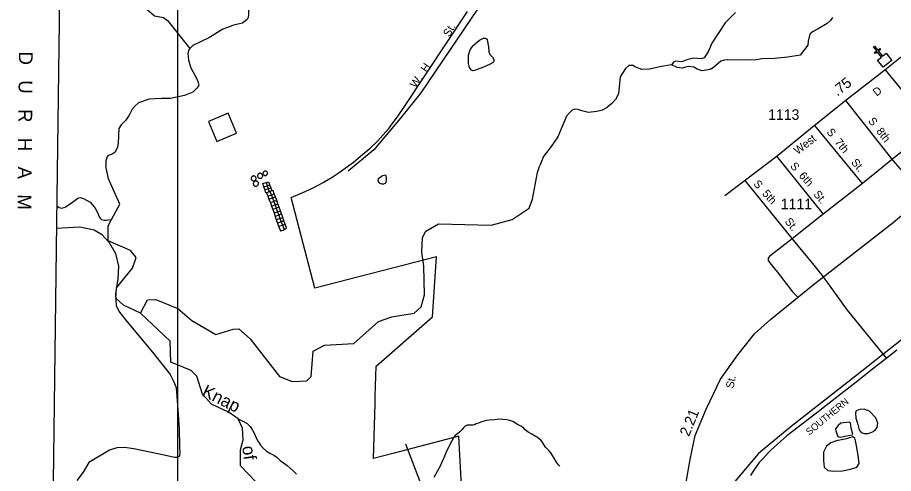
# Model space of a CAD drawing. Extents: x 2056842 to 2160602, y 826753 to 1016856.
# Drawn here: x 2057378 to 2067778, y 860868 to 866278 of the extents above; entities that cross this region are included whole.
import ezdxf

# ---------------------------------------------------------------- set-up
doc = ezdxf.new("R2010")
doc.units = 0
for name, color, linetype in [('Exist Boundary Land Use Reservation Military US Department of Defense', 7, 'Continuous'), ('Exist Boundary Political City Limit New', 7, 'Continuous'), ('Exist Boundary Political CountyLine', 7, 'Continuous'), ('Exist Boundary Political CountyLine Label', 7, 'Continuous'), ('Exist Cultural Church CELL', 7, 'Continuous'), ('Exist Hydrographic Creek Single Shore', 7, 'Continuous'), ('Exist Hydrographic Creek Single Shore Label', 7, 'Continuous'), ('Exist Hydrographic Misc Water Feature', 7, 'Continuous'), ('Exist Railroad Mainline', 7, 'Continuous'), ('Exist Railroad Mainline Label', 7, 'Continuous'), ('Exist Road Non-System Type 51', 7, 'Continuous'), ('Exist Road Non-System Type 51 Label', 7, 'Continuous'), ('Exist Road Secondary Mileage Hundredths English Label', 7, 'Continuous'), ('Exist Road Secondary Type 51 Attributed', 7, 'Continuous'), ('Exist Road Secondary Type 51 Label', 7, 'Continuous'), ('Exist Road Secondary Type 51 Number Label', 7, 'Continuous'), ('Map Preparation Boundary City Limit Buffer Line', 7, 'Continuous'), ('Map Preparation Inset Cut Line', 7, 'Continuous')]:
    doc.layers.add(name, color=color, linetype=linetype)

msp = doc.modelspace()

# ---------------------------------------------------------------- linework, layer by layer
at = {"layer": 'Exist Boundary Land Use Reservation Military US Department of Defense'}
msp.add_lwpolyline([(2068119, 862646), (2067327, 862022), (2066562, 861424), (2066175, 861104), (2065853, 860720)], dxfattribs=at)
at = {"layer": 'Exist Boundary Political City Limit New'}
for points in [[(2061626, 861786), (2061636, 862140), (2062304, 862726), (2062353, 863437), (2060909, 863065), (2060628, 864143), (2060756, 864197), (2060887, 864258), (2061006, 864321), (2061116, 864385), (2061208, 864447), (2061239, 864469), (2061367, 864563), (2061475, 864651), (2061566, 864729), (2061653, 864812), (2061717, 864881), (2061791, 864966), (2061815, 865000), (2061888, 865101), (2061972, 865223), (2062721, 866349)], [(2062676, 860203), (2062618, 861310), (2061851, 861109), (2061604, 861044), (2061623, 861697), (2061626, 861786)]]:
    msp.add_lwpolyline(points, dxfattribs=at)
at = {"layer": 'Exist Boundary Political CountyLine'}
msp.add_lwpolyline([(2058297, 904796), (2058304, 899211), (2058216, 894228), (2058154, 887047), (2058114, 884097), (2057934, 870695), (2057845, 864146), (2057782, 859231), (2057748, 856800), (2057704, 853375), (2057690, 853331), (2057682, 853305), (2057672, 853284), (2057665, 853266), (2057651, 853246), (2057635, 853225), (2057616, 853207), (2057583, 853188)], dxfattribs=at)
at = {"layer": 'Exist Cultural Church CELL'}
msp.add_lwpolyline([(2067590, 865774), (2067635, 865809), (2067588, 865869), (2067563, 865850), (2067553, 865862), (2067579, 865882), (2067542, 865930), (2067554, 865939), (2067591, 865892), (2067617, 865911), (2067626, 865899), (2067601, 865879), (2067648, 865819), (2067693, 865854), (2067759, 865770), (2067655, 865690)], close=True, dxfattribs=at)
at = {"layer": 'Exist Hydrographic Creek Single Shore'}
for points in [[(2060205, 867203), (2060148, 866697), (2060125, 866448), (2060120, 866318), (2060116, 866278)], [(2065904, 866337), (2065782, 866215), (2065622, 865972), (2065578, 865871), (2065531, 865798), (2065496, 865786), (2065407, 865794), (2065324, 865777), (2065264, 865753), (2065192, 865761), (2065169, 865753), (2065144, 865717)], [(2060116, 866278), (2060104, 866254), (2060048, 866213), (2059944, 866189), (2059913, 866177), (2059815, 866140), (2059656, 866041), (2059458, 865945), (2059423, 865910)], [(2067056, 866279), (2067032, 866243), (2066992, 866207), (2066886, 866144), (2066816, 866108), (2066784, 866080), (2066764, 865996), (2066760, 865952), (2066669, 865832), (2066523, 865806), (2066365, 865791), (2066221, 865787), (2066147, 865775), (2066051, 865771), (2065811, 865778), (2065767, 865774), (2065727, 865762), (2065643, 865686), (2065603, 865662), (2065507, 865646), (2065447, 865664), (2065407, 865690), (2065347, 865696), (2065311, 865688), (2065275, 865679), (2065212, 865685), (2065144, 865717)], [(2059423, 865910), (2059411, 865896), (2059401, 865850), (2059409, 865772), (2059437, 865682), (2059509, 865549), (2059524, 865509), (2059532, 865476), (2059509, 865438), (2059461, 865392), (2059362, 865354), (2059195, 865318), (2059083, 865317), (2058942, 865310), (2058816, 865264), (2058773, 865227), (2058740, 865190), (2058702, 865120), (2058665, 865061), (2058608, 865004), (2058583, 864961), (2058573, 864793), (2058567, 864741), (2058539, 864679), (2058501, 864655), (2058454, 864642), (2058443, 864627), (2058428, 864577), (2058426, 864547), (2058427, 864519)], [(2065144, 865717), (2065003, 865695), (2064883, 865667), (2064791, 865663), (2064707, 865694), (2064687, 865710), (2064635, 865710), (2064595, 865674), (2064535, 865574), (2064512, 865374), (2064478, 865304), (2064438, 865260), (2064378, 865210), (2064318, 865178), (2064258, 865162), (2064158, 865153), (2064078, 865169), (2064036, 865185), (2063992, 865189), (2063962, 865177), (2063926, 865145), (2063896, 865109), (2063792, 864861), (2063715, 864749), (2063625, 864630), (2063581, 864522)], [(2058839, 862771), (2058638, 862864), (2058547, 862948), (2058555, 863072), (2058745, 863305), (2058788, 863432), (2058720, 863515), (2058454, 863629), (2058454, 863806), (2058493, 863881), (2058595, 864063), (2058460, 864364), (2058427, 864519)], [(2058839, 862771), (2058922, 862930), (2059021, 862931), (2059280, 862824), (2059447, 862683), (2059731, 862517), (2059938, 862581), (2060006, 862583), (2060139, 862465), (2060489, 862019), (2060640, 861960), (2060814, 861969), (2060864, 862017), (2060890, 862319), (2061023, 862391), (2061373, 862411), (2061664, 862670), (2061821, 862726), (2062088, 862770), (2062171, 862844), (2062212, 862987), (2062203, 863329), (2062178, 863496), (2062186, 863670), (2062227, 863745), (2062378, 863830), (2063003, 863814), (2063253, 863881), (2063452, 864015), (2063493, 864122), (2063551, 864439), (2063581, 864522)], [(2060209, 860768), (2060025, 860958), (2060025, 861149), (2060058, 861266), (2060050, 861407), (2059999, 861517), (2059890, 861591), (2059683, 861691), (2059573, 861808), (2059507, 862022), (2059440, 862089), (2059198, 862190), (2059190, 862439), (2058839, 862771)], [(2059999, 861517), (2060062, 861486), (2060106, 861460), (2060141, 861426), (2060168, 861381), (2060191, 861337), (2060213, 861292), (2060235, 861247), (2060263, 861206), (2060296, 861168), (2060333, 861134), (2060376, 861109), (2060421, 861086), (2060460, 861056), (2060498, 861023), (2060538, 860993), (2060578, 860963), (2060617, 860931), (2060654, 860897), (2060690, 860862)], [(2063818, 860953), (2063801, 860969), (2063777, 861001), (2063749, 861051), (2063709, 861113), (2063689, 861137), (2063671, 861157), (2063647, 861181), (2063635, 861199), (2063607, 861243), (2063591, 861263), (2063576, 861277), (2063547, 861299), (2063525, 861312), (2063485, 861336), (2063443, 861360), (2063405, 861388), (2063384, 861408), (2063354, 861428), (2063321, 861446), (2063289, 861466), (2063260, 861484), (2063225, 861498), (2063188, 861504), (2063138, 861510), (2063092, 861512), (2063040, 861506), (2062978, 861501), (2062946, 861496), (2062887, 861479), (2062850, 861467), (2062823, 861457), (2062804, 861447), (2062785, 861443), (2062765, 861441), (2062752, 861441), (2062732, 861443), (2062715, 861441), (2062695, 861429), (2062673, 861409), (2062655, 861387), (2062643, 861375), (2062626, 861359), (2062605, 861343), (2062576, 861319), (2062559, 861301), (2062529, 861246), (2062495, 861181), (2062465, 861114), (2062441, 861052), (2062417, 861003), (2062395, 860954), (2062361, 860893), (2062320, 860821)]]:
    msp.add_lwpolyline(points, dxfattribs=at)
at = {"layer": 'Exist Hydrographic Misc Water Feature'}
for p, q in [((2059743, 864808), (2059979, 864906)), ((2060304, 864270), (2060342, 864282)), ((2060316, 864236), (2060304, 864270)), ((2060330, 864319), (2060342, 864282)), ((2060342, 864282), (2060372, 864292)), ((2060342, 864282), (2060354, 864246)), ((2060354, 864246), (2060384, 864256)), ((2060372, 864292), (2060384, 864256)), ((2060384, 864256), (2060398, 864221)), ((2060316, 864236), (2060354, 864246)), ((2060366, 864210), (2060334, 864200)), ((2060334, 864200), (2060350, 864161)), ((2060350, 864161), (2060392, 864172)), ((2060350, 864161), (2060364, 864122)), ((2060354, 864246), (2060366, 864210)), ((2060398, 864221), (2060376, 864215)), ((2060376, 864215), (2060392, 864172)), ((2060392, 864172), (2060425, 864187)), ((2060392, 864172), (2060406, 864137)), ((2060406, 864137), (2060442, 864149)), ((2060456, 864109), (2060442, 864149)), ((2060364, 864122), (2060406, 864137)), ((2060364, 864122), (2060380, 864080)), ((2060420, 864097), (2060380, 864080)), ((2060394, 864041), (2060436, 864055)), ((2060406, 864137), (2060420, 864097)), ((2060456, 864109), (2060420, 864097)), ((2060420, 864097), (2060436, 864055)), ((2060436, 864055), (2060470, 864067)), ((2060436, 864055), (2060450, 864015)), ((2060484, 864027), (2060470, 864067)), ((2060394, 864041), (2060408, 864001)), ((2060450, 864015), (2060408, 864001)), ((2060408, 864001), (2060424, 863961)), ((2060424, 863961), (2060466, 863972)), ((2060424, 863961), (2060436, 863919)), ((2060484, 864027), (2060450, 864015)), ((2060450, 864015), (2060466, 863972)), ((2060466, 863972), (2060500, 863985)), ((2060466, 863972), (2060480, 863935)), ((2060514, 863947), (2060480, 863935)), ((2060500, 863985), (2060484, 864027)), ((2060514, 863947), (2060500, 863985)), ((2060480, 863935), (2060436, 863919)), ((2060436, 863919), (2060450, 863881)), ((2060450, 863881), (2060494, 863895)), ((2060510, 863855), (2060464, 863839)), ((2060464, 863839), (2060478, 863801)), ((2060480, 863935), (2060494, 863895)), ((2060494, 863895), (2060528, 863905)), ((2060494, 863895), (2060510, 863855)), ((2060542, 863867), (2060510, 863855)), ((2060510, 863855), (2060525, 863815)), ((2060542, 863867), (2060528, 863905)), ((2060556, 863827), (2060542, 863867)), ((2060478, 863801), (2060525, 863815)), ((2060525, 863815), (2060556, 863827)), ((2060525, 863815), (2060543, 863763))]:
    msp.add_line(p, q, dxfattribs=at)
for points in [[(2057891, 867490), (2058055, 867172), (2058231, 866826), (2058332, 866695), (2058362, 866643), (2058378, 866599), (2058410, 866563), (2058498, 866495), (2058634, 866405), (2058674, 866422), (2058718, 866473), (2058768, 866482), (2058814, 866472), (2058850, 866452), (2058890, 866396), (2058972, 866326), (2059006, 866300), (2059112, 866279), (2059160, 866242), (2059423, 865911)], [(2062912, 865691), (2062804, 865648), (2062784, 865646), (2062767, 865653), (2062743, 865687), (2062732, 865734), (2062733, 865831), (2062751, 865894), (2062787, 865945), (2062865, 866009), (2062912, 866035), (2062929, 866033), (2062946, 866027), (2062953, 866013), (2062971, 865929), (2062974, 865870), (2062986, 865839), (2063019, 865807), (2063032, 865779), (2063033, 865760), (2063027, 865743), (2062991, 865724), (2062912, 865691)], [(2059769, 865096), (2059646, 865043), (2059743, 864808)], [(2059979, 864906), (2059878, 865142), (2059769, 865096)], [(2060186, 864398), (2060182, 864398), (2060176, 864396), (2060170, 864396), (2060164, 864392), (2060160, 864388), (2060158, 864384), (2060156, 864378), (2060154, 864374), (2060154, 864368), (2060154, 864362), (2060158, 864356), (2060160, 864350), (2060164, 864348), (2060168, 864344), (2060172, 864342), (2060178, 864340), (2060184, 864340), (2060188, 864342), (2060194, 864344), (2060200, 864346), (2060204, 864350), (2060206, 864354), (2060208, 864360), (2060210, 864364), (2060210, 864370), (2060210, 864376), (2060208, 864382), (2060204, 864388), (2060198, 864392), (2060194, 864396), (2060190, 864396), (2060186, 864398)], [(2060263, 864431), (2060257, 864431), (2060253, 864429), (2060246, 864427), (2060240, 864425), (2060236, 864421), (2060234, 864417), (2060230, 864411), (2060229, 864405), (2060228, 864399), (2060229, 864395), (2060231, 864389), (2060233, 864383), (2060237, 864379), (2060240, 864377), (2060242, 864373), (2060248, 864371), (2060253, 864371), (2060259, 864369), (2060264, 864371), (2060269, 864371), (2060275, 864373), (2060279, 864377), (2060283, 864383), (2060287, 864387), (2060289, 864391), (2060288, 864395), (2060289, 864401), (2060288, 864405), (2060287, 864409), (2060286, 864413), (2060285, 864417), (2060280, 864421), (2060274, 864425), (2060268, 864429), (2060263, 864431)], [(2060327, 864455), (2060320, 864457), (2060317, 864457), (2060310, 864455), (2060305, 864453), (2060301, 864449), (2060296, 864443), (2060293, 864437), (2060292, 864431), (2060293, 864427), (2060292, 864421), (2060296, 864415), (2060301, 864411), (2060302, 864407), (2060309, 864405), (2060315, 864403), (2060320, 864403), (2060325, 864403), (2060331, 864405), (2060336, 864407), (2060338, 864411), (2060342, 864415), (2060344, 864419), (2060347, 864425), (2060346, 864431), (2060344, 864437), (2060345, 864441), (2060341, 864445), (2060338, 864449), (2060334, 864453), (2060331, 864455), (2060327, 864455)], [(2061693, 864385), (2061662, 864364), (2061658, 864343), (2061672, 864316), (2061698, 864303), (2061727, 864304), (2061748, 864314), (2061759, 864335), (2061758, 864377), (2061750, 864405), (2061738, 864409), (2061713, 864400), (2061693, 864385)], [(2060201, 864278), (2060207, 864276), (2060211, 864276), (2060217, 864276), (2060223, 864280), (2060228, 864284), (2060233, 864288), (2060237, 864292), (2060236, 864296), (2060239, 864300), (2060239, 864307), (2060239, 864310), (2060239, 864316), (2060237, 864322), (2060233, 864328), (2060226, 864332), (2060223, 864334), (2060219, 864336), (2060212, 864338), (2060209, 864338), (2060202, 864338), (2060199, 864338), (2060193, 864334), (2060189, 864330), (2060185, 864326), (2060183, 864322), (2060179, 864316), (2060177, 864310), (2060177, 864304), (2060179, 864300), (2060180, 864294), (2060183, 864288), (2060186, 864284), (2060191, 864282), (2060196, 864278), (2060201, 864278)], [(2060304, 864270), (2060292, 864307), (2060330, 864319)], [(2060330, 864319), (2060359, 864329), (2060372, 864296), (2060372, 864292)], [(2060334, 864200), (2060328, 864198), (2060316, 864236)], [(2060376, 864215), (2060370, 864212), (2060366, 864210)], [(2060425, 864187), (2060412, 864227), (2060398, 864221)], [(2060442, 864149), (2060433, 864169), (2060425, 864187)], [(2057844, 864045), (2057873, 864023), (2057905, 864017), (2057943, 864029), (2058030, 864088), (2058093, 864136), (2058119, 864142), (2058163, 864132), (2058240, 864087), (2058288, 864031), (2058310, 864001), (2058330, 863955), (2058344, 863923), (2058361, 863897), (2058377, 863883), (2058407, 863873), (2058434, 863875), (2058456, 863879), (2058493, 863881)], [(2060380, 864080), (2060384, 864066), (2060394, 864041)], [(2060470, 864067), (2060460, 864095), (2060456, 864109)], [(2060528, 863905), (2060520, 863929), (2060514, 863947)], [(2060450, 863881), (2060462, 863845), (2060464, 863839)], [(2060478, 863801), (2060499, 863749), (2060505, 863749), (2060517, 863751), (2060532, 863757), (2060543, 863763)], [(2060543, 863763), (2060552, 863767), (2060572, 863781), (2060556, 863827)], [(2067352, 861466), (2067371, 861388), (2067394, 861354), (2067432, 861344), (2067478, 861344), (2067520, 861357), (2067556, 861380), (2067586, 861414), (2067592, 861464), (2067569, 861530), (2067493, 861606), (2067430, 861631), (2067379, 861627), (2067337, 861612), (2067326, 861589), (2067333, 861525), (2067352, 861466)], [(2067278, 861407), (2067269, 861471), (2067252, 861477), (2067155, 861466), (2067120, 861439), (2067090, 861397), (2067096, 861376), (2067113, 861314), (2067128, 861302), (2067155, 861298), (2067202, 861312), (2067290, 861325), (2067295, 861335), (2067278, 861407)], [(2067219, 861281), (2067103, 861255), (2067035, 861232), (2066985, 861194), (2066949, 861120), (2066947, 861021), (2066955, 860945), (2066999, 860903), (2067071, 860897), (2067174, 860901), (2067267, 860918), (2067345, 860943), (2067371, 860985), (2067360, 861084), (2067330, 861241), (2067318, 861289), (2067295, 861302), (2067244, 861289), (2067219, 861281)]]:
    msp.add_lwpolyline(points, dxfattribs=at)
at = {"layer": 'Exist Railroad Mainline'}
msp.add_lwpolyline([(2067817, 862332), (2067722, 862256), (2067494, 862077), (2067392, 861995), (2067315, 861935), (2067230, 861870), (2067156, 861814), (2066980, 861675), (2066884, 861599), (2066786, 861523), (2066648, 861416), (2066514, 861313), (2066363, 861182), (2066323, 861145), (2066290, 861112), (2066227, 861043), (2066184, 860998), (2066149, 860948), (2066111, 860895), (2066082, 860846)], dxfattribs=at)
at = {"layer": 'Exist Road Non-System Type 51'}
for p, q in [((2067679, 865659), (2068254, 864952)), ((2067210, 865293), (2067771, 864581)), ((2067410, 864309), (2066843, 864998)), ((2066391, 864635), (2066944, 863943))]:
    msp.add_line(p, q, dxfattribs=at)
for points in [[(2063128, 866745), (2063066, 866682), (2062940, 866527), (2062165, 865385), (2061925, 865082), (2061608, 864708), (2061305, 864455)], [(2067771, 864581), (2067909, 864423), (2068132, 864148)], [(2066013, 864345), (2066572, 863658)], [(2057840, 863778), (2058120, 863795), (2058289, 863760), (2058376, 863708), (2058467, 863608), (2058541, 863478), (2058576, 863326), (2058571, 863178), (2058541, 863000), (2058549, 862857), (2058589, 862783), (2058680, 862666), (2058982, 862309), (2059190, 862044), (2059229, 861962), (2059260, 861888), (2059273, 861731), (2059296, 861401), (2059301, 861184), (2059305, 861114), (2059301, 861075), (2059279, 861058), (2059244, 861058), (2059118, 861084), (2058758, 861162), (2058649, 861175), (2058558, 861171), (2058471, 861145), (2058224, 860997), (2058156, 860884), (2058083, 860784)], [(2066572, 863658), (2066832, 863340), (2066945, 863201), (2067228, 862804), (2067696, 862232)], [(2066375, 863287), (2066385, 863275), (2066578, 863024), (2066642, 862960)], [(2064026, 856175), (2063635, 856406), (2063477, 856536), (2063384, 856778), (2063272, 857160), (2063282, 857532), (2063338, 858520), (2063356, 859022), (2063356, 859255), (2063179, 859538), (2063003, 859781), (2062723, 860023), (2062481, 860144), (2062323, 860321), (2062165, 860749), (2061988, 861215)]]:
    msp.add_lwpolyline(points, dxfattribs=at)
at = {"layer": 'Exist Road Secondary Type 51 Attributed'}
for points in [[(2068882, 866614), (2068677, 866452), (2068494, 866306), (2068053, 865955), (2067674, 865655), (2067196, 865282), (2066794, 864959), (2066396, 864632), (2065775, 864161)], [(2069430, 865913), (2069291, 865800), (2069053, 865610), (2068603, 865256), (2068231, 864962), (2067772, 864600), (2067596, 864460), (2067390, 864292), (2066925, 863928), (2066574, 863653), (2066329, 863461), (2066307, 863442), (2066291, 863421), (2066292, 863396), (2066311, 863366), (2066375, 863287)], [(2064684, 855840), (2064643, 855944), (2064589, 856125), (2064579, 856312), (2064609, 856569), (2064801, 857754), (2065030, 859013), (2065227, 860248), (2065365, 861035), (2065425, 861318), (2065554, 861630), (2065725, 861986), (2065931, 862277), (2066130, 862526), (2066317, 862697), (2066825, 863107), (2067775, 863846), (2068132, 864148), (2068556, 864441), (2069020, 864778), (2069627, 865267), (2069800, 865437)]]:
    msp.add_lwpolyline(points, dxfattribs=at)
at = {"layer": 'Map Preparation Boundary City Limit Buffer Line'}
for points in [[(2061626, 861786), (2061636, 862140), (2062304, 862726), (2062353, 863437), (2060909, 863065), (2060628, 864143), (2060756, 864197), (2060887, 864258), (2061006, 864321), (2061116, 864385), (2061208, 864447), (2061239, 864469), (2061367, 864563), (2061475, 864651), (2061566, 864729), (2061653, 864812), (2061717, 864881), (2061791, 864966), (2061815, 865000), (2061888, 865101), (2061972, 865223), (2062721, 866349)], [(2062676, 860203), (2062618, 861310), (2061851, 861109), (2061604, 861044), (2061623, 861697), (2061626, 861786)]]:
    msp.add_lwpolyline(points, dxfattribs=at)
at = {"layer": 'Map Preparation Inset Cut Line'}
msp.add_lwpolyline([(2059277, 845852), (2104036, 845852), (2104036, 868311), (2085975, 868309), (2085982, 877260), (2059277, 877260), (2059277, 845852)], dxfattribs=at)

# ---------------------------------------------------------------- texts
at = {"layer": 'Exist Boundary Political CountyLine Label'}
msp.add_text('D   U   R   H   A   M', height=164.04, rotation=269.5008, dxfattribs=at).set_placement((2057395, 865875))
at = {"layer": 'Exist Hydrographic Creek Single Shore Label'}
for s, rotation, p in [('Knap', 333.4761, (2059556, 861795)), ('of', 277.9265, (2060045, 861187))]:
    msp.add_text(s, height=150, rotation=rotation, dxfattribs=at).set_placement(p)
at = {"layer": 'Exist Railroad Mainline Label'}
msp.add_text('SOUTHERN', height=82, rotation=39.4764, dxfattribs=at).set_placement((2066780, 861317))
at = {"layer": 'Exist Road Non-System Type 51 Label'}
for s, rotation, p in [('St.', 60.128, (2062506, 866040)), ('W.  H', 55.6525, (2062108, 865434)), ('S  8th', 308.0923, (2067472, 865049)), ('S  7th', 308.9173, (2066978, 864918)), ('St.', 309.5547, (2067270, 864557)), ('S  6th', 312.1663, (2066545, 864511)), ('S  5th', 312.1663, (2066109, 864299)), ('St.', 309.5547, (2066822, 864179)), ('St.', 309.5547, (2066481, 863855))]:
    msp.add_text(s, height=95, rotation=rotation, dxfattribs=at).set_placement(p)
at = {"layer": 'Exist Road Secondary Mileage Hundredths English Label'}
for s, rotation, p in [('.75', 37.9498, (2067111, 865338)), ('2.21', 67.557, (2065350, 861299))]:
    msp.add_text(s, height=125, rotation=rotation, dxfattribs=at).set_placement(p)
at = {"layer": 'Exist Road Secondary Type 51 Label'}
for s, rotation, p in [('D', 38.2886, (2067579, 865338)), ('West', 37.5874, (2066640, 864647)), ('St.', 79.0253, (2065879, 861872))]:
    msp.add_text(s, height=95, rotation=rotation, dxfattribs=at).set_placement(p)
at = {"layer": 'Exist Road Secondary Type 51 Number Label'}
for s, p in [('1113', (2066290, 865064)), ('1111', (2066440, 864003))]:
    msp.add_text(s, height=125, dxfattribs=at).set_placement(p)

doc.saveas('drawing.dxf')
